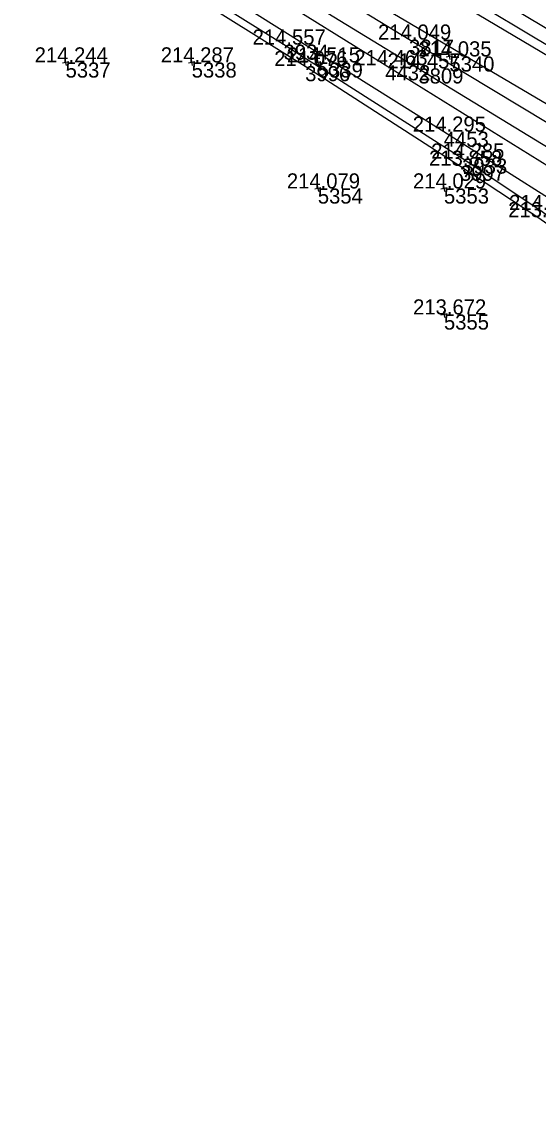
# Model space of a CAD drawing. Extents: x -556590 to -554855, y -1137918 to -1135717.
# Drawn here: x -556143.5 to -556102.5, y -1136102.8 to -1136016.8 of the extents above; entities that cross this region are included whole.
import ezdxf

# ---------------------------------------------------------------- set-up
doc = ezdxf.new("R2010")
doc.units = 0
for name, color, linetype in [('Vrstva 4', 7, 'Continuous'), ('Vrstva 49', 7, 'Continuous'), ('Vrstva 51', 7, 'Continuous'), ('Vrstva 60', 7, 'Continuous'), ('Vrstva 61', 7, 'Continuous')]:
    doc.layers.add(name, color=color, linetype=linetype)

msp = doc.modelspace()

# ---------------------------------------------------------------- linework, layer by layer
at = {"layer": 'Vrstva 4'}
for points in [[(-556035.076, -1136060.042), (-556053.045, -1136047.75), (-556072.52, -1136035.259), (-556090.871, -1136023.901), (-556119.06, -1136007.015), (-556136.13, -1135996.934), (-556151.339, -1135987.753)], [(-556151.93, -1135988.593), (-556136.171, -1135998.151), (-556118.936, -1136008.33), (-556090.998, -1136025.072), (-556072.555, -1136036.367), (-556052.586, -1136049.221), (-556035.578, -1136060.814)]]:
    msp.add_lwpolyline(points, dxfattribs=at)
at = {"layer": 'Vrstva 49'}
for p, q in [((-556139.754, -1136019.953), (-556140.246, -1136020.047)), ((-556140.047, -1136019.754), (-556139.953, -1136020.246)), ((-556129.754, -1136019.953), (-556130.246, -1136020.047)), ((-556130.047, -1136019.754), (-556129.953, -1136020.246)), ((-556119.754, -1136019.953), (-556120.246, -1136020.047)), ((-556120.047, -1136019.754), (-556119.953, -1136020.246)), ((-556109.321, -1136019.475), (-556109.813, -1136019.569)), ((-556109.614, -1136019.276), (-556109.52, -1136019.768)), ((-556119.754, -1136029.953), (-556120.246, -1136030.047)), ((-556120.047, -1136029.754), (-556119.953, -1136030.246)), ((-556109.754, -1136029.953), (-556110.246, -1136030.047)), ((-556110.047, -1136029.754), (-556109.953, -1136030.246)), ((-556110.047, -1136039.754), (-556109.953, -1136040.246)), ((-556109.754, -1136039.953), (-556110.246, -1136040.047))]:
    msp.add_line(p, q, dxfattribs=at)
for points in [[(-556152.444, -1135989.696), (-556134.35, -1136000.06), (-556112.219, -1136013.229), (-556086.098, -1136028.771), (-556062.361, -1136043.618), (-556050.236, -1136051.53), (-556035.99, -1136061.647)], [(-556038.363, -1136064.437), (-556052.689, -1136054.344), (-556074.014, -1136041.014), (-556093.919, -1136027.981), (-556117.008, -1136014.334), (-556137.507, -1136001.817), (-556153.921, -1135992.126)], [(-556042.927, -1136063.033), (-556051.216, -1136057.072), (-556070.993, -1136043.91), (-556090.728, -1136031.496), (-556112.772, -1136018.185), (-556132.305, -1136006.25), (-556154.277, -1135993.121)], [(-556154.655, -1135994.416), (-556134.329, -1136006.842), (-556112.025, -1136020.47), (-556087.44, -1136035.48), (-556065.043, -1136049.58), (-556049.085, -1136059.974), (-556042.927, -1136063.033)], [(-556147.907, -1136003.683), (-556139.608, -1136008.963), (-556130.967, -1136014.044), (-556121.003, -1136020.29), (-556108.729, -1136028.193), (-556102.549, -1136032.278), (-556097.33, -1136035.954), (-556095.352, -1136037.769), (-556093.332, -1136039.909), (-556091.363, -1136042.7), (-556089.441, -1136045.759), (-556085.615, -1136053.263)], [(-556084.992, -1136053.136), (-556087.43, -1136048.225), (-556089.401, -1136044.379), (-556091.05, -1136041.85), (-556093.51, -1136038.765), (-556096.714, -1136035.837), (-556102.386, -1136031.711), (-556108.555, -1136027.624), (-556122.719, -1136018.582), (-556135.84, -1136010.37), (-556147.628, -1136003.161)]]:
    msp.add_lwpolyline(points, dxfattribs=at)
at = {"layer": 'Vrstva 51'}
for points in [[(-556003.109, -1136102.758), (-556006.375, -1136101.225), (-556010.882, -1136098.948), (-556015.231, -1136096.337), (-556020.327, -1136093.013), (-556028.542, -1136087.117), (-556040.188, -1136079.041), (-556043.827, -1136076.734), (-556048.783, -1136074.01), (-556065.089, -1136065.628), (-556077.857, -1136058.711), (-556079.979, -1136057.374), (-556081.878, -1136055.64), (-556083.273, -1136053.979), (-556084.513, -1136051.523), (-556088.912, -1136041.262), (-556090.343, -1136038.92), (-556092.002, -1136037.117), (-556093.982, -1136035.652), (-556110.016, -1136025.492), (-556130.533, -1136012.591), (-556156.21, -1135997.017)], [(-556020.931, -1136090.347), (-556037.809, -1136078.372), (-556042.535, -1136075.223), (-556047.808, -1136072.231), (-556065.635, -1136063.04), (-556077.899, -1136056.26), (-556079.86, -1136054.619), (-556081.334, -1136052.905), (-556082.602, -1136050.669), (-556085.661, -1136043.137), (-556087.32, -1136039.611), (-556088.581, -1136037.601), (-556090.361, -1136035.586), (-556092.441, -1136034.014), (-556114.655, -1136020.216), (-556135.009, -1136007.539)]]:
    msp.add_lwpolyline(points, dxfattribs=at)
at = {"layer": 'Vrstva 60'}
for p, q in [((-556112.772, -1136018.185), (-556112.772, -1136018.185)), ((-556122.719, -1136018.582), (-556122.719, -1136018.582)), ((-556140, -1136020), (-556140, -1136020)), ((-556130, -1136020), (-556130, -1136020)), ((-556120, -1136020), (-556120, -1136020)), ((-556109.567, -1136019.522), (-556109.567, -1136019.522)), ((-556121.003, -1136020.29), (-556121.003, -1136020.29)), ((-556114.655, -1136020.216), (-556114.655, -1136020.216)), ((-556112.025, -1136020.47), (-556112.025, -1136020.47)), ((-556110.016, -1136025.492), (-556110.016, -1136025.492)), ((-556108.555, -1136027.624), (-556108.555, -1136027.624)), ((-556108.729, -1136028.193), (-556108.729, -1136028.193)), ((-556120, -1136030), (-556120, -1136030)), ((-556110, -1136030), (-556110, -1136030)), ((-556102.549, -1136032.278), (-556102.549, -1136032.278)), ((-556110, -1136040), (-556110, -1136040))]:
    msp.add_line(p, q, dxfattribs=at)

# ---------------------------------------------------------------- texts
for s, p in [('3817', (-556112.772, -1136019.385)), ('3934', (-556122.719, -1136019.782)), ('5337', (-556140, -1136021.2)), ('5338', (-556130, -1136021.2)), ('5339', (-556120, -1136021.2)), ('5340', (-556109.567, -1136020.722)), ('3996', (-556121.003, -1136021.49)), ('4432', (-556114.655, -1136021.416)), ('3809', (-556112.025, -1136021.67)), ('4453', (-556110.016, -1136026.692)), ('3933', (-556108.555, -1136028.824)), ('3997', (-556108.729, -1136029.393)), ('5354', (-556120, -1136031.2)), ('5353', (-556110, -1136031.2)), ('5355', (-556110, -1136041.2))]:
    msp.add_text(s, height=1.2, dxfattribs=at).set_placement(p)
at = {"layer": 'Vrstva 61'}
for s, p in [('214.557', (-556125.171, -1136018.582)), ('214.049', (-556115.226, -1136018.185)), ('214.035', (-556112.023, -1136019.522)), ('214.244', (-556142.451, -1136020)), ('214.287', (-556132.452, -1136020)), ('214.076', (-556123.455, -1136020.29)), ('214.515', (-556122.456, -1136020)), ('214.463', (-556117.107, -1136020.216)), ('214.457', (-556114.477, -1136020.47)), ('214.295', (-556112.472, -1136025.492)), ('213.858', (-556111.183, -1136028.193)), ('214.285', (-556111.011, -1136027.624)), ('214.079', (-556122.454, -1136030)), ('214.029', (-556112.454, -1136030)), ('213.781', (-556104.906, -1136032.278)), ('214.182', (-556104.834, -1136031.711)), ('213.672', (-556112.448, -1136040))]:
    msp.add_text(s, height=1.2, dxfattribs=at).set_placement(p)

doc.saveas('drawing.dxf')
